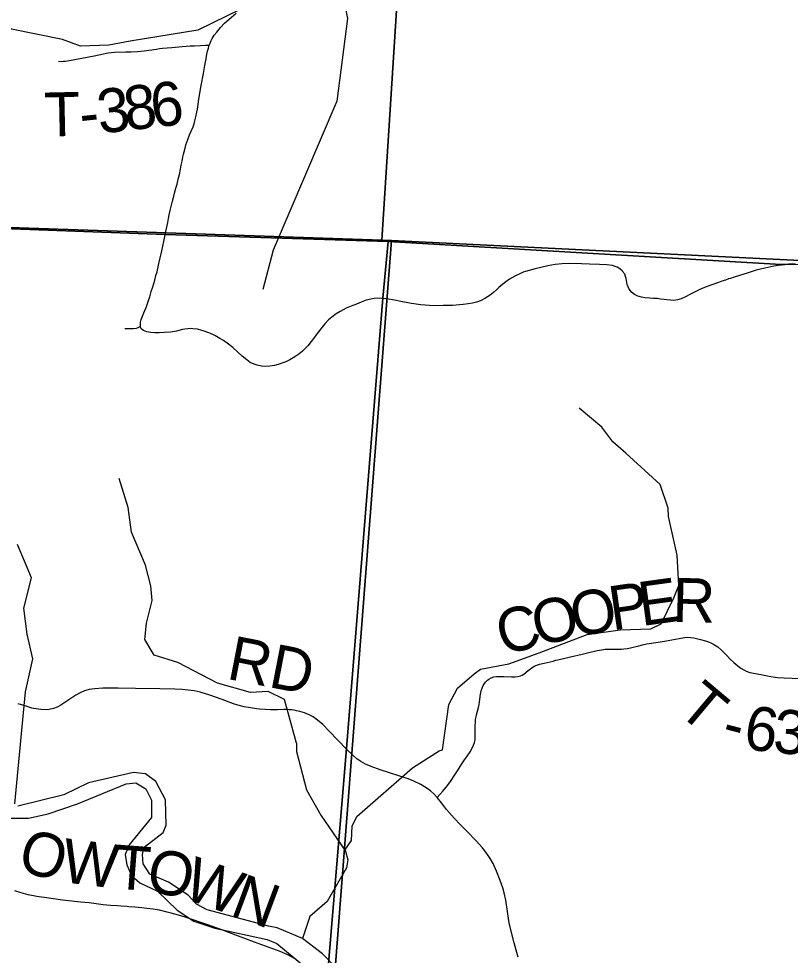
# Model space of a CAD drawing. Extents: x 0 to 34, y 0 to 22.
# Drawn here: x 25.892 to 26.889, y 15.061 to 16.271 of the extents above; entities that cross this region are included whole.
import ezdxf

# ---------------------------------------------------------------- set-up
doc = ezdxf.new("R2010")
doc.units = 0
for name, color, linetype in [('Default', 7, 'Continuous'), ('GM_X_County_Road', 7, 'Continuous'), ('GM_X_County_Road_Text', 7, 'Continuous'), ('GM_X_Major_River', 7, 'Continuous'), ('GM_X_Minor_River', 7, 'Continuous'), ('GM_X_Section', 7, 'Continuous'), ('GM_X_Township_Road', 7, 'Continuous'), ('GM_X_Township_Road_Text', 7, 'Continuous')]:
    doc.layers.add(name, color=color, linetype=linetype)

msp = doc.modelspace()

# ---------------------------------------------------------------- linework, layer by layer
at = {"layer": 'Default'}
for points in [[(27.7198, 20.9), (23.5167, 20.9), (23.5167, 16.1239), (23.5888, 16.1195), (25.0535, 16.0331), (25.3458, 16.0191), (26.0811, 15.9921), (26.3691, 15.9829), (26.8773, 15.953), (26.8866, 15.9536), (26.8953, 15.9537)], [(26.8953, 15.9537), (26.8866, 15.9536), (26.8773, 15.953), (26.3691, 15.9829), (26.3625, 15.9099), (26.3153, 15.3279), (26.29, 15.0246), (26.2331, 14.1), (29.5051, 14.1)]]:
    msp.add_lwpolyline(points, dxfattribs=at)
msp.add_lwpolyline([(23.5167, 16.1239), (23.5167, 14.1), (26.2331, 14.1), (26.29, 15.0246), (26.3153, 15.3279), (26.3625, 15.9099), (26.3691, 15.9829), (26.0811, 15.9921), (25.3458, 16.0191), (25.0535, 16.0331), (23.5888, 16.1195)], close=True, dxfattribs=at)
at = {"layer": 'GM_X_County_Road'}
for points in [[(26.1381, 16.2365), (26.1391, 16.2391), (26.1406, 16.2423), (26.1419, 16.245), (26.1444, 16.2492), (26.1477, 16.2534), (26.1528, 16.2592), (26.158, 16.2647), (26.1727, 16.2779)], [(26.0813, 15.9915), (26.0821, 15.9958), (26.0844, 16.0073), (26.0855, 16.0125), (26.0863, 16.0172), (26.0876, 16.0231), (26.0887, 16.0281), (26.0905, 16.0349), (26.0922, 16.0413), (26.0933, 16.0455), (26.095, 16.0517), (26.0965, 16.0569), (26.098, 16.0633), (26.0996, 16.0696), (26.1009, 16.0763), (26.102, 16.0814), (26.103, 16.0867), (26.1041, 16.0921), (26.1049, 16.0956), (26.1056, 16.0988), (26.1069, 16.1035), (26.108, 16.1077), (26.1092, 16.1111), (26.1104, 16.1147), (26.1127, 16.1206), (26.1146, 16.1254), (26.1171, 16.1312), (26.1184, 16.1348), (26.1195, 16.1386), (26.1208, 16.1437), (26.1222, 16.15), (26.1228, 16.1539), (26.1233, 16.157), (26.1248, 16.1667), (26.1277, 16.1843), (26.1306, 16.1998), (26.1315, 16.2052), (26.1322, 16.2101), (26.1332, 16.2148), (26.1339, 16.219), (26.1349, 16.2247), (26.1358, 16.2289), (26.1369, 16.2328), (26.1381, 16.2365)], [(26.3627, 15.9094), (26.3611, 15.9095), (26.3555, 15.9096), (26.3514, 15.9093), (26.3468, 15.9085), (26.3409, 15.907), (26.3342, 15.9046), (26.3283, 15.9021), (26.3236, 15.9002), (26.3151, 15.8966), (26.3073, 15.8926), (26.3019, 15.8894), (26.2964, 15.8853), (26.2922, 15.8816), (26.2875, 15.8765), (26.2824, 15.8702), (26.2763, 15.8624), (26.2742, 15.8593), (26.2716, 15.856), (26.2682, 15.8514), (26.2659, 15.8486), (26.2621, 15.8445), (26.2584, 15.8412), (26.2537, 15.8373), (26.2501, 15.8348), (26.2465, 15.8325), (26.2422, 15.83), (26.2372, 15.8277), (26.2332, 15.8261), (26.2273, 15.8242), (26.2226, 15.8229), (26.2165, 15.8218), (26.211, 15.8216), (26.2055, 15.822), (26.2001, 15.823), (26.196, 15.8244), (26.1911, 15.8268), (26.1865, 15.8299), (26.1808, 15.8346), (26.1684, 15.8459), (26.1611, 15.8517), (26.1582, 15.8539), (26.1566, 15.8549), (26.1518, 15.8578), (26.1453, 15.8615), (26.1425, 15.8629), (26.1397, 15.8642), (26.1374, 15.8651), (26.1315, 15.8672), (26.1285, 15.8681), (26.1231, 15.8695), (26.1169, 15.8702), (26.1135, 15.8704), (26.1106, 15.8702), (26.1067, 15.8696), (26.1036, 15.8691), (26.0956, 15.867), (26.088, 15.866), (26.0799, 15.8653), (26.0732, 15.8651), (26.0676, 15.8651), (26.0628, 15.8655), (26.0576, 15.8662), (26.0531, 15.868), (26.0514, 15.8691), (26.0502, 15.8702), (26.0498, 15.8711), (26.0494, 15.8723), (26.0492, 15.8734), (26.0491, 15.8761), (26.0494, 15.8787), (26.0503, 15.8822), (26.0519, 15.8866), (26.0536, 15.8906), (26.055, 15.894), (26.0564, 15.8978), (26.0573, 15.9004), (26.0594, 15.9066), (26.0611, 15.9116), (26.0631, 15.9183), (26.065, 15.9245), (26.0676, 15.933), (26.0692, 15.9388), (26.0706, 15.9438), (26.0726, 15.9522), (26.0748, 15.9619), (26.0759, 15.9668), (26.0776, 15.9747), (26.08, 15.985), (26.0813, 15.9915)], [(26.8763, 15.9523), (26.8678, 15.9511), (26.856, 15.9486), (26.8448, 15.9458), (26.8345, 15.9425), (26.8162, 15.9368), (26.8115, 15.9353), (26.8091, 15.9345), (26.805, 15.9331), (26.8003, 15.9316), (26.7962, 15.9301), (26.7804, 15.9244), (26.773, 15.9212), (26.7678, 15.9188), (26.765, 15.9174), (26.7591, 15.9146), (26.7534, 15.9115), (26.748, 15.9089), (26.7432, 15.9074), (26.7383, 15.9069), (26.7341, 15.907), (26.7295, 15.9075), (26.726, 15.9079), (26.7213, 15.9086), (26.717, 15.9093), (26.7122, 15.9095), (26.7075, 15.9097), (26.7015, 15.9103), (26.6965, 15.9111), (26.6918, 15.9123), (26.6875, 15.9144), (26.6839, 15.9176), (26.6809, 15.9213), (26.6793, 15.9242), (26.6781, 15.9275), (26.6768, 15.9353), (26.676, 15.9377), (26.675, 15.9405), (26.674, 15.9422), (26.6729, 15.9436), (26.6717, 15.9451), (26.6688, 15.9476), (26.665, 15.9498), (26.6626, 15.9508), (26.659, 15.9517), (26.652, 15.9527), (26.6422, 15.9532), (26.6296, 15.9537), (26.6189, 15.954), (26.6035, 15.9543), (26.5941, 15.9542), (26.5853, 15.9532), (26.5757, 15.9514), (26.5592, 15.9476), (26.5469, 15.9442), (26.5439, 15.9431), (26.5393, 15.9413), (26.5338, 15.9385), (26.5262, 15.9342), (26.5215, 15.9309), (26.5174, 15.9277), (26.5123, 15.9233), (26.5091, 15.9205), (26.5055, 15.9171), (26.5013, 15.9138), (26.4944, 15.9091), (26.4884, 15.9063), (26.4833, 15.9044), (26.4781, 15.9031), (26.4728, 15.9023), (26.466, 15.9014), (26.4523, 15.9004), (26.4405, 15.9001), (26.4294, 15.9), (26.4229, 15.9003), (26.4115, 15.9012), (26.3993, 15.9029), (26.3855, 15.9055), (26.3776, 15.9071), (26.3697, 15.9086), (26.3627, 15.9094)], [(26.9905, 15.952), (26.9872, 15.9505), (26.9825, 15.9493), (26.9765, 15.9491), (26.9645, 15.949), (26.9556, 15.9489), (26.9418, 15.9494), (26.9325, 15.9498), (26.9257, 15.9504), (26.9207, 15.9511), (26.9175, 15.9514), (26.9053, 15.9527), (26.8956, 15.9532), (26.8868, 15.953), (26.8775, 15.9525), (26.8763, 15.9523)], [(26.3155, 15.3273), (26.2932, 15.3507), (26.2847, 15.359), (26.2781, 15.3647), (26.2725, 15.3688), (26.2671, 15.3718), (26.2612, 15.3742), (26.2552, 15.376), (26.251, 15.3769), (26.248, 15.3775), (26.2443, 15.3779), (26.2412, 15.3781), (26.2369, 15.3783), (26.2345, 15.3783), (26.2264, 15.3782), (26.2171, 15.3782), (26.2036, 15.379), (26.1993, 15.3794), (26.1913, 15.3805), (26.1889, 15.381), (26.1834, 15.382), (26.1769, 15.3837), (26.1709, 15.3855), (26.1645, 15.3876), (26.1616, 15.3886), (26.1546, 15.3912), (26.1388, 15.3969), (26.1263, 15.4009), (26.1184, 15.4027), (26.111, 15.4036), (26.1029, 15.4041), (26.0936, 15.4046), (26.0743, 15.4052), (26.0427, 15.4057), (26.0203, 15.4061), (26.0098, 15.4062), (26.0004, 15.406), (25.9899, 15.4052), (25.9831, 15.4041), (25.977, 15.4024), (25.9712, 15.4), (25.9657, 15.3971), (25.9579, 15.392), (25.9462, 15.384), (25.9414, 15.3814), (25.9368, 15.3798), (25.9314, 15.3786), (25.9259, 15.3781), (25.9204, 15.3783), (25.9144, 15.3792), (25.9108, 15.3799), (25.909, 15.3804), (25.9013, 15.3826), (25.8912, 15.3859)], [(26.5372, 15.0586), (26.5348, 15.0676), (26.5323, 15.0772), (26.5277, 15.094), (26.5256, 15.103), (26.5247, 15.1085), (26.5234, 15.1177), (26.5212, 15.1324), (26.5193, 15.1416), (26.5175, 15.1482), (26.5142, 15.1576), (26.5093, 15.1697), (26.505, 15.1794), (26.5013, 15.186), (26.4985, 15.19), (26.4956, 15.1941), (26.491, 15.2), (26.4831, 15.2088), (26.4706, 15.2217), (26.4623, 15.2301), (26.4545, 15.2381), (26.4448, 15.2493), (26.438, 15.2581), (26.4326, 15.265), (26.4287, 15.2692), (26.4241, 15.2733), (26.4185, 15.2774), (26.4115, 15.2815), (26.4026, 15.2859), (26.3951, 15.2889), (26.3845, 15.2925), (26.3708, 15.2966), (26.359, 15.3004), (26.3474, 15.3047), (26.3401, 15.308), (26.3341, 15.3112), (26.329, 15.3147), (26.3239, 15.3191), (26.3155, 15.3273)]]:
    msp.add_lwpolyline(points, dxfattribs=at)
at = {"layer": 'GM_X_Major_River'}
for points in [[(26.3385, 15.0072), (26.2843, 15.0631), (26.2585, 15.0828), (26.2259, 15.0967), (26.2146, 15.0986), (26.1354, 15.1199), (26.1218, 15.1271), (26.1108, 15.1385), (26.0854, 15.1554), (26.0611, 15.166), (26.0528, 15.1792), (26.052, 15.191), (26.0538, 15.2008), (26.0784, 15.2195), (26.0825, 15.229), (26.0817, 15.262), (26.0692, 15.2854), (26.0555, 15.2952), (26.04, 15.2971), (25.9821, 15.2837), (25.95, 15.2684), (25.8906, 15.2535)], [(25.8498, 15.2382), (25.9046, 15.2383), (25.93, 15.2437), (25.9678, 15.2567), (26.0309, 15.2823), (26.0434, 15.2838), (26.0563, 15.2759), (26.0635, 15.2615), (26.0636, 15.2388), (26.0345, 15.2038), (26.0296, 15.1913), (26.0316, 15.1777), (26.0377, 15.164), (26.0483, 15.1546), (26.0714, 15.144), (26.0968, 15.1195), (26.118, 15.1051), (26.1453, 15.0961), (26.2131, 15.0815), (26.2252, 15.0762), (26.2605, 15.0475)]]:
    msp.add_lwpolyline(points, dxfattribs=at)
at = {"layer": 'GM_X_Minor_River'}
for points in [[(26.1935, 16.3026), (26.1966, 16.2917), (26.1235, 16.2558), (26.036, 16.2415), (26.0085, 16.2365), (25.9717, 16.2351), (25.9486, 16.2438), (25.8827, 16.2572), (25.8535, 16.288), (25.8155, 16.3387), (25.8045, 16.3689)], [(26.3049, 16.3303), (26.3169, 16.2708), (26.3031, 16.164), (26.2206, 15.9716), (26.2072, 15.921)], [(26.4397, 15.3262), (26.4477, 15.3848), (26.459, 15.4061), (26.4803, 15.4247), (26.4886, 15.4305), (26.525, 15.4373), (26.5644, 15.4518), (26.6266, 15.4755), (26.6691, 15.4812), (26.7089, 15.4828), (26.7222, 15.4893), (26.7385, 15.5227), (26.7449, 15.5387), (26.7427, 15.5779), (26.7317, 15.6277), (26.7309, 15.6383), (26.7207, 15.6691), (26.6764, 15.7094), (26.6597, 15.7242), (26.6453, 15.7432), (26.6161, 15.7678)], [(26.2507, 15.3348), (26.2354, 15.3914), (26.2142, 15.4017), (26.1914, 15.4005), (26.1486, 15.4126), (26.0974, 15.4392), (26.0671, 15.4487), (26.055, 15.4688), (26.0569, 15.4901), (26.0641, 15.5194), (26.0626, 15.5384), (26.0558, 15.565), (26.0376, 15.6076), (26.0334, 15.6395), (26.0217, 15.6767)], [(25.8868, 15.2567), (25.9007, 15.4013), (25.9102, 15.4439), (25.9026, 15.4759), (25.8984, 15.5093), (25.9083, 15.5485), (25.8901, 15.5914)], [(26.2507, 15.3348), (26.2507, 15.3241), (26.2636, 15.2748), (26.2823, 15.2419), (26.3141, 15.1957), (26.3172, 15.1844), (26.3154, 15.1741), (26.2906, 15.1303), (26.268, 15.1112), (26.2585, 15.0828)], [(26.3133, 15.197), (26.322, 15.2091), (26.3227, 15.228), (26.329, 15.2402), (26.4008, 15.3033), (26.4352, 15.3251), (26.4397, 15.3262)]]:
    msp.add_lwpolyline(points, dxfattribs=at)
at = {"layer": 'GM_X_Section'}
for points in [[(26.4248, 16.9831), (26.3613, 15.9846), (25.3091, 16.0203), (25.3722, 17.0086), (25.8848, 17.0085)], [(27.484, 16.9363), (27.4673, 16.6748), (27.4216, 15.9328), (26.3734, 15.9843), (26.3613, 15.9846), (26.4248, 16.9831)], [(25.3091, 16.0203), (26.3613, 15.9846), (26.3734, 15.9843), (26.2944, 14.9601), (25.2534, 15.0128)], [(26.3734, 15.9843), (27.4216, 15.9328), (27.4099, 15.6936), (27.392, 15.4391), (27.3753, 15.1787), (27.3574, 14.9107), (27.3572, 14.9074), (26.2944, 14.9601)]]:
    msp.add_lwpolyline(points, close=True, dxfattribs=at)
at = {"layer": 'GM_X_Township_Road'}
for points in [[(25.9434, 16.2158), (25.9472, 16.2155), (25.9496, 16.2157), (25.9521, 16.2159), (25.9576, 16.2167), (25.9734, 16.2196), (25.9892, 16.2229), (26.0015, 16.2253), (26.0076, 16.2264), (26.0156, 16.2273), (26.0304, 16.2278), (26.0373, 16.2279), (26.0452, 16.2283), (26.0497, 16.2287), (26.0538, 16.2291), (26.0571, 16.2294), (26.0602, 16.2299), (26.0639, 16.2305), (26.0663, 16.2309), (26.0697, 16.2315), (26.0737, 16.2321), (26.0775, 16.2325), (26.0835, 16.2331), (26.0897, 16.2335), (26.1031, 16.2347), (26.1084, 16.2351), (26.1135, 16.2354), (26.1189, 16.2357), (26.1267, 16.2362), (26.1332, 16.2365), (26.1381, 16.2365)], [(26.0292, 15.8707), (26.0329, 15.8704), (26.0354, 15.8704), (26.0399, 15.8706), (26.0439, 15.8711), (26.0464, 15.872), (26.0492, 15.8734)], [(26.4326, 15.265), (26.4359, 15.2686), (26.4401, 15.2732), (26.446, 15.2804), (26.4508, 15.2869), (26.4556, 15.294), (26.459, 15.2992), (26.4646, 15.3082), (26.4681, 15.3133), (26.4705, 15.3169), (26.4751, 15.3236), (26.4778, 15.3284), (26.4796, 15.3323), (26.4808, 15.3358), (26.4816, 15.3395), (26.4818, 15.3432), (26.4818, 15.3575), (26.482, 15.3624), (26.4823, 15.3655), (26.483, 15.3692), (26.4835, 15.3716), (26.4847, 15.3764), (26.486, 15.3812), (26.4869, 15.3848), (26.4875, 15.3885), (26.4887, 15.3984), (26.4895, 15.4026), (26.4906, 15.4062), (26.4921, 15.4096), (26.4937, 15.4122), (26.4953, 15.4142), (26.4975, 15.4163), (26.4995, 15.4178), (26.5022, 15.4193), (26.5058, 15.4205), (26.5094, 15.4211), (26.5131, 15.4213), (26.5187, 15.4211), (26.5287, 15.4205), (26.533, 15.4205), (26.5367, 15.4209), (26.5403, 15.4219), (26.5426, 15.4229), (26.5446, 15.4243), (26.5504, 15.429), (26.5548, 15.4324), (26.558, 15.4343), (26.5614, 15.4358), (26.565, 15.437), (26.571, 15.4385), (26.5825, 15.441), (26.5861, 15.442), (26.5886, 15.4425), (26.6049, 15.4465), (26.62, 15.4499), (26.6285, 15.4519), (26.6393, 15.4546), (26.6454, 15.4557), (26.6497, 15.4562), (26.6547, 15.4563), (26.6646, 15.4563), (26.6683, 15.4564), (26.6708, 15.4566), (26.6739, 15.4569), (26.6782, 15.4574), (26.6825, 15.4582), (26.6933, 15.4609), (26.6981, 15.4621), (26.7036, 15.4632), (26.7184, 15.4653), (26.7263, 15.4667), (26.7452, 15.4702), (26.752, 15.4714), (26.7563, 15.4717), (26.76, 15.4715), (26.7643, 15.4709), (26.7727, 15.4689), (26.7793, 15.4672), (26.7834, 15.4658), (26.7873, 15.4641), (26.7911, 15.462), (26.7952, 15.4592), (26.7999, 15.4552), (26.8063, 15.4488), (26.8114, 15.4436), (26.8158, 15.4393), (26.821, 15.4348), (26.8249, 15.4318), (26.8287, 15.4296), (26.832, 15.4279), (26.8367, 15.4263), (26.8438, 15.4248), (26.855, 15.4229), (26.8637, 15.4213), (26.8722, 15.4199), (26.8809, 15.4194), (26.9017, 15.4187)], [(26.2484, 15.0569), (26.2395, 15.0615), (26.2297, 15.0658), (26.2202, 15.0693), (26.1966, 15.078), (26.1724, 15.0871), (26.1543, 15.0938), (26.1364, 15.1004), (26.1084, 15.1099), (26.1012, 15.1121), (26.0938, 15.1142), (26.0889, 15.1155), (26.0836, 15.1169), (26.074, 15.1192), (26.0656, 15.1207), (26.0576, 15.1216), (26.0508, 15.1224), (26.0465, 15.1229), (26.0417, 15.1232), (26.0343, 15.1238), (26.0318, 15.124), (26.0244, 15.1245), (26.0194, 15.1247), (26.0104, 15.1254), (26.0012, 15.1263), (25.983, 15.1288), (25.9719, 15.1298), (25.9484, 15.1324), (25.9306, 15.1346), (25.9152, 15.1369), (25.9042, 15.1391), (25.8952, 15.1415), (25.887, 15.1444)]]:
    msp.add_lwpolyline(points, dxfattribs=at)

# ---------------------------------------------------------------- texts
at = {"layer": 'GM_X_County_Road_Text'}
msp.add_text('RD', height=0.05682, rotation=348.9822, dxfattribs=at).set_placement((26.1592, 15.4183))
at = {"layer": 'GM_X_Township_Road_Text'}
for s, rotation, p in [('8', 6.4735, (26.0308, 16.126)), ('6', 6.5027, (26.0653, 16.1299)), ('T', 1.2332, (25.9253, 16.1184)), ('3', 6.3814, (25.9962, 16.1221)), ('-', 5.978, (25.9728, 16.1196)), ('E', 7.848, (26.6967, 15.4861)), ('R', 358.7197, (26.7364, 15.4918)), ('O', 11.0106, (26.6105, 15.4712)), ('P', 8.2655, (26.6588, 15.4806)), ('O', 13.1448, (26.5623, 15.4599)), ('C', 15.1618, (26.5178, 15.4479)), ('T', 319.9519, (26.741, 15.3755)), ('6', 351.5629, (26.8269, 15.3284)), ('3', 355.2612, (26.8655, 15.3228)), ('-', 345.4327, (26.7978, 15.3356)), ('O', 344.1316, (25.8882, 15.1715)), ('W', 352.8935, (25.9456, 15.1559)), ('T', 355.6405, (26.0139, 15.1475)), ('O', 349.1734, (26.0546, 15.1445)), ('W', 340.6512, (26.1016, 15.1357)), ('N', 339.536, (26.1634, 15.114))]:
    msp.add_text(s, height=0.0568, rotation=rotation, dxfattribs=at).set_placement(p)

doc.saveas('drawing.dxf')
